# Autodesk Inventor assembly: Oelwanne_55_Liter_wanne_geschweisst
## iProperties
Created: 2005-05
Part Number: Oelwanne_55_Liter_wanne_geschweisst
Document SubType Name: Weldment
Designer: Mario Wipf
Manufacturer: Standard
Standards Organization: Custom
Author: Mario Wipf
